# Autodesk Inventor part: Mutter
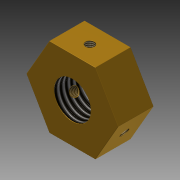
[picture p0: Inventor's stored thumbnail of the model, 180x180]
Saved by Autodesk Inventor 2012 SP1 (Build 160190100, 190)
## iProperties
Created: 2012-10
Part Number: Mutter
Material: Default
Document SubType Name: Modeling
Designer: Dominic Mähling
Density: 1 g/cm^3
Author: Dominic Mähling
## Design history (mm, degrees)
derived "Funkenstrecke master.ipt"
feature "Mutter::Funkenstrecke master.ipt" dims "d0" = 10
tag "Bezeichnung1"
node "Volumenkörper1"
